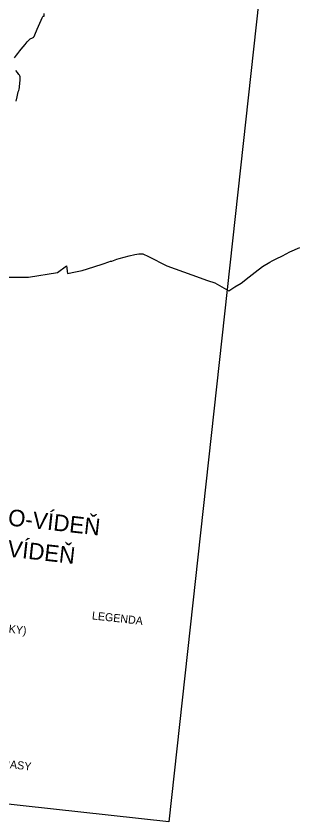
# Model space of a CAD drawing. Extents: x -678204 to -526855, y -1228851 to -1110393.
# Drawn here: x -610673 to -602154, y -1222167 to -1198003 of the extents above; entities that cross this region are included whole.
import ezdxf

# ---------------------------------------------------------------- set-up
doc = ezdxf.new("R2010")
doc.units = 0
for name, color, linetype in [('00_n_cyklo prujezdne rekreacni hlavni', 7, 'Continuous'), ('00_n_cyklo trasovani rekreacni hlavni', 7, 'Continuous'), ('00_n_legenda popisy', 7, 'Continuous'), ('00_n_legenda popisy_hlavni', 7, 'Continuous'), ('_HELP BIG', 7, 'Continuous')]:
    doc.layers.add(name, color=color, linetype=linetype)

msp = doc.modelspace()

# ---------------------------------------------------------------- linework, layer by layer
at = {"layer": '00_n_cyklo prujezdne rekreacni hlavni'}
for points in [[(-610720, -1199254), (-610659, -1199171), (-610623, -1199127), (-610557, -1199044), (-610519, -1198997), (-610403, -1198857), (-610339, -1198775), (-610271, -1198702), (-610249, -1198686), (-610183, -1198655), (-610163, -1198648), (-610145, -1198636), (-610136, -1198624), (-610130, -1198610), (-610109, -1198561), (-610041, -1198396), (-609920, -1198129), (-609892, -1198058), (-609880, -1198033), (-609872, -1198018), (-609862, -1198007), (-609831, -1198006), (-609835, -1197923)], [(-610675, -1200552), (-610642, -1200423), (-610608, -1200278), (-610596, -1200234), (-610586, -1200195), (-610575, -1200146), (-610574, -1200127), (-610570, -1200091), (-610566, -1200039), (-610561, -1199997), (-610559, -1199978), (-610556, -1199954), (-610553, -1199918), (-610551, -1199878), (-610549, -1199844), (-610551, -1199822), (-610562, -1199791), (-610570, -1199773), (-610588, -1199749), (-610630, -1199696), (-610680, -1199638)], [(-604105, -1206124), (-603914, -1206010), (-603677, -1205820), (-603496, -1205686), (-603280, -1205514), (-603056, -1205384), (-602991, -1205337), (-602862, -1205281), (-602676, -1205190), (-602456, -1205074), (-602154, -1204940)], [(-610970, -1205836), (-610297, -1205831), (-609430, -1205693), (-609163, -1205495), (-609128, -1205723), (-608895, -1205671), (-608693, -1205632), (-608339, -1205525), (-608055, -1205430), (-607891, -1205369), (-607835, -1205348), (-607800, -1205352), (-607649, -1205296), (-607580, -1205270), (-607283, -1205192), (-607110, -1205149), (-606994, -1205127), (-606869, -1205127), (-606696, -1205213), (-606153, -1205489), (-605394, -1205761), (-604928, -1205929), (-604704, -1205997), (-604286, -1206239), (-604105, -1206124)]]:
    msp.add_lwpolyline(points, dxfattribs=at)
at = {"layer": '00_n_cyklo trasovani rekreacni hlavni'}
for points in [[(-610720, -1199254), (-610659, -1199171), (-610623, -1199127), (-610557, -1199044), (-610519, -1198997), (-610403, -1198857), (-610339, -1198775), (-610271, -1198702), (-610249, -1198686), (-610183, -1198655), (-610163, -1198648), (-610145, -1198636), (-610136, -1198624), (-610130, -1198610), (-610109, -1198561), (-610041, -1198396), (-609920, -1198129), (-609892, -1198058), (-609880, -1198033), (-609872, -1198018), (-609862, -1198007), (-609831, -1198006), (-609835, -1197923)], [(-610675, -1200552), (-610642, -1200423), (-610608, -1200278), (-610596, -1200234), (-610586, -1200195), (-610575, -1200146), (-610574, -1200127), (-610570, -1200091), (-610566, -1200039), (-610561, -1199997), (-610559, -1199978), (-610556, -1199954), (-610553, -1199918), (-610551, -1199878), (-610549, -1199844), (-610551, -1199822), (-610562, -1199791), (-610570, -1199773), (-610588, -1199749), (-610630, -1199696), (-610680, -1199638)], [(-604105, -1206124), (-603914, -1206010), (-603677, -1205820), (-603496, -1205686), (-603280, -1205514), (-603056, -1205384), (-602991, -1205337), (-602862, -1205281), (-602676, -1205190), (-602456, -1205074), (-602154, -1204940)], [(-610970, -1205836), (-610297, -1205831), (-609430, -1205693), (-609163, -1205495), (-609128, -1205723), (-608895, -1205671), (-608693, -1205632), (-608339, -1205525), (-608055, -1205430), (-607891, -1205369), (-607835, -1205348), (-607800, -1205352), (-607649, -1205296), (-607580, -1205270), (-607283, -1205192), (-607110, -1205149), (-606994, -1205127), (-606869, -1205127), (-606696, -1205213), (-606153, -1205489), (-605394, -1205761), (-604928, -1205929), (-604704, -1205997), (-604286, -1206239), (-604105, -1206124)]]:
    msp.add_lwpolyline(points, dxfattribs=at)
at = {"layer": '_HELP BIG'}
msp.add_lwpolyline([(-626233, -1219955), (-623127, -1191667), (-602982, -1193879), (-606088, -1222167)], close=True, dxfattribs=at)

# ---------------------------------------------------------------- texts
at = {"layer": '00_n_legenda popisy'}
for s, p in [('HLAVNÍ REKREAČNÍ TRASY (PRŮJEZDNÉ ÚSEKY) ', (-618013, -1215705)), ('LEGENDA', (-608406, -1216092)), ('VEDLEJŠÍ REKREAČNÍ TRASY ', (-614837, -1220117))]:
    msp.add_text(s, height=240, rotation=353.6836, dxfattribs=at).set_placement(p)
at = {"layer": '00_n_legenda popisy_hlavni'}
for s, p in [('KORIDOR JMK CSBV BRNO-VÍDEŇ', (-619092, -1212372)), ('KORIDOR JMK EV9 BRNO-MIKULOV-VÍDEŇ', (-622490, -1212932))]:
    msp.add_text(s, height=497.66, rotation=353.6836, dxfattribs=at).set_placement(p)

doc.saveas('drawing.dxf')
